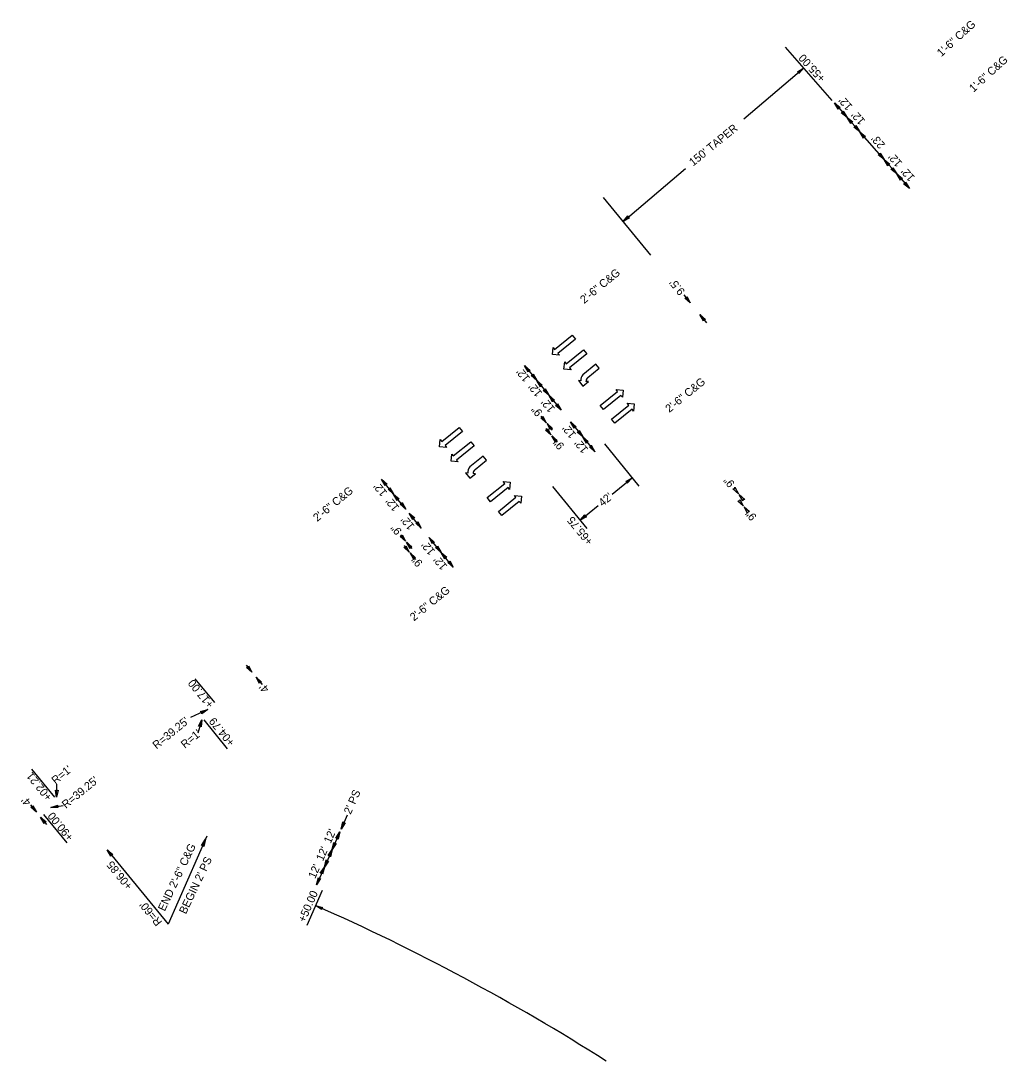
# Model space of a CAD drawing. Extents: x 2320991 to 2332664, y 598057 to 612602.
# Drawn here: x 2326449 to 2327065, y 601774 to 602424 of the extents above; entities that cross this region are included whole.
import ezdxf

# ---------------------------------------------------------------- set-up
doc = ezdxf.new("R2010")
doc.units = 0
for name, color, linetype in [('Prop Dimension', 7, 'Continuous'), ('Prop Dimension Text', 7, 'Continuous'), ('Prop Lane Arrow CELL', 7, 'Continuous'), ('Prop Terminator CELL', 7, 'Continuous')]:
    doc.layers.add(name, color=color, linetype=linetype)

msp = doc.modelspace()

# ---------------------------------------------------------------- linework, layer by layer
at = {"layer": 'Prop Dimension'}
for p, q in [((2326900.93, 602362.35), (2326938.22, 602394.1)), ((2326957.38, 602372.26), (2326965.3, 602363.24)), ((2326965.3, 602363.24), (2326973.22, 602354.23)), ((2326988.4, 602336.94), (2326973.22, 602354.23)), ((2326825.51, 602298.13), (2326864.46, 602331.29)), ((2326988.41, 602336.94), (2326996.33, 602327.92)), ((2326996.33, 602327.92), (2327004.25, 602318.91)), ((2326842.73, 602277.26), (2326813.11, 602313.14)), ((2326863.3, 602252.42), (2326867.41, 602247.39)), ((2326873.42, 602240.03), (2326877.53, 602234.99)), ((2326763.89, 602208.21), (2326771.48, 602198.91)), ((2326771.48, 602198.91), (2326779.07, 602189.62)), ((2326779.07, 602189.62), (2326786.66, 602180.32)), ((2326774.11, 602176.6), (2326777.43, 602172.54)), ((2326777.06, 602168.99), (2326780.37, 602164.93)), ((2326777.9, 602171.96), (2326781.21, 602167.9)), ((2326792.63, 602173.01), (2326800.22, 602163.71)), ((2326780.85, 602164.35), (2326784.16, 602160.3)), ((2326800.22, 602163.71), (2326807.81, 602154.41)), ((2326813.81, 602159.25), (2326835.31, 602132.9)), ((2326682.06, 602127.92), (2326674.47, 602137.21)), ((2326818.53, 602127.94), (2326831.03, 602138.15)), ((2326781.27, 602132.68), (2326802.78, 602106.34)), ((2326689.65, 602118.62), (2326682.06, 602127.92)), ((2326798.5, 602111.59), (2326809.8, 602120.82)), ((2326699.35, 602106.75), (2326691.76, 602116.05)), ((2326686.29, 602102.58), (2326689.6, 602098.53)), ((2326690.07, 602097.95), (2326693.38, 602093.89)), ((2326711.78, 602091.51), (2326704.19, 602100.8)), ((2326688.58, 602095.78), (2326691.89, 602091.73)), ((2326692.36, 602091.15), (2326695.67, 602087.09)), ((2326719.37, 602082.21), (2326711.78, 602091.51)), ((2326589.93, 602021.13), (2326593.59, 602016.64)), ((2326570.37, 601997.68), (2326558.17, 602012.63)), ((2326596.12, 602013.54), (2326599.91, 602008.9)), ((2326565.94, 601993.4), (2326555.22, 601988.4)), ((2326562.31, 601987.02), (2326559.8, 601978.66)), ((2326563.44, 601986.86), (2326578.11, 601968.9)), ((2326470.38, 601938.64), (2326456.1, 601956.13)), ((2326471.57, 601938.53), (2326471.75, 601946.76)), ((2326455.26, 601933.78), (2326458.93, 601929.3)), ((2326467.94, 601932.16), (2326475.64, 601933.45)), ((2326461.46, 601926.2), (2326465.25, 601921.55)), ((2326463.41, 601927.88), (2326477.88, 601910.15)), ((2326653.16, 601927.46), (2326649.3, 601918.71)), ((2326648.49, 601916.89), (2326643.65, 601905.91)), ((2326565.36, 601914.18), (2326541.16, 601859.27)), ((2326503.22, 601905.75), (2326541.16, 601859.27)), ((2326643.65, 601905.91), (2326638.81, 601894.93)), ((2326638.81, 601894.93), (2326633.97, 601883.94)), ((2326637.41, 601880.24), (2326627.85, 601858.55))]:
    msp.add_line(p, q, dxfattribs=at)
msp.add_lwpolyline([(2326956.07, 602373.76), (2326926.85, 602407.04)], dxfattribs=at)
msp.add_arc((2326088.93, 600635.5), 1350, 57.47144, 66.2198, dxfattribs=at)
at = {"layer": 'Prop Lane Arrow CELL'}
for p, q in [((2326782.66, 602218.35), (2326793.53, 602227.17)), ((2326793.53, 602227.17), (2326795.61, 602224.61)), ((2326795.61, 602224.61), (2326784.74, 602215.79)), ((2326781.29, 602215.05), (2326781.72, 602219.52)), ((2326785.69, 602214.62), (2326781.29, 602215.05)), ((2326781.72, 602219.52), (2326782.66, 602218.35)), ((2326784.74, 602215.79), (2326785.69, 602214.62)), ((2326789.87, 602209.3), (2326800.74, 602218.12)), ((2326802.82, 602215.56), (2326791.95, 602206.74)), ((2326800.74, 602218.12), (2326802.82, 602215.56)), ((2326788.49, 602206), (2326788.92, 602210.47)), ((2326788.92, 602210.47), (2326789.87, 602209.3)), ((2326808.45, 602209.14), (2326800.28, 602202.47)), ((2326810.54, 602206.58), (2326808.45, 602209.14)), ((2326792.89, 602205.57), (2326788.49, 602206)), ((2326791.95, 602206.74), (2326792.89, 602205.57)), ((2326803.45, 602200.8), (2326810.54, 602206.58)), ((2326798.94, 602198.66), (2326797.46, 602198.81)), ((2326797.46, 602198.81), (2326800.2, 602195.37)), ((2326800.2, 602195.37), (2326803.72, 602198.17)), ((2326803.72, 602198.17), (2326802.24, 602198.32)), ((2326811.1, 602183.28), (2326821.97, 602192.11)), ((2326824.05, 602189.54), (2326813.18, 602180.72)), ((2326821.97, 602192.11), (2326821.02, 602193.27)), ((2326821.02, 602193.27), (2326825.42, 602192.85)), ((2326824.99, 602188.38), (2326824.05, 602189.54)), ((2326825.42, 602192.85), (2326824.99, 602188.38)), ((2326813.18, 602180.72), (2326811.1, 602183.28)), ((2326818.09, 602174.71), (2326828.96, 602183.54)), ((2326828.96, 602183.54), (2326828.02, 602184.7)), ((2326828.02, 602184.7), (2326832.42, 602184.28)), ((2326832.42, 602184.28), (2326831.99, 602179.81)), ((2326831.04, 602180.97), (2326820.17, 602172.15)), ((2326831.99, 602179.81), (2326831.04, 602180.97)), ((2326712.15, 602160.79), (2326723.02, 602169.61)), ((2326723.02, 602169.61), (2326725.1, 602167.05)), ((2326820.17, 602172.15), (2326818.09, 602174.71)), ((2326725.1, 602167.05), (2326714.23, 602158.23)), ((2326710.78, 602157.48), (2326711.21, 602161.95)), ((2326715.18, 602157.06), (2326710.78, 602157.48)), ((2326711.21, 602161.95), (2326712.15, 602160.79)), ((2326714.23, 602158.23), (2326715.18, 602157.06)), ((2326719.36, 602151.74), (2326730.23, 602160.56)), ((2326732.31, 602158), (2326721.44, 602149.18)), ((2326730.23, 602160.56), (2326732.31, 602158)), ((2326717.98, 602148.43), (2326718.41, 602152.9)), ((2326718.41, 602152.9), (2326719.36, 602151.74)), ((2326721.44, 602149.18), (2326722.38, 602148.01)), ((2326737.94, 602151.58), (2326729.77, 602144.9)), ((2326740.03, 602149.02), (2326737.94, 602151.58)), ((2326722.38, 602148.01), (2326717.98, 602148.43)), ((2326732.94, 602143.23), (2326740.03, 602149.02)), ((2326728.43, 602141.1), (2326726.95, 602141.24)), ((2326726.95, 602141.24), (2326729.69, 602137.8)), ((2326729.69, 602137.8), (2326733.21, 602140.61)), ((2326733.21, 602140.61), (2326731.73, 602140.76)), ((2326740.59, 602125.72), (2326751.46, 602134.54)), ((2326753.54, 602131.98), (2326742.67, 602123.16)), ((2326751.46, 602134.54), (2326750.51, 602135.71)), ((2326750.51, 602135.71), (2326754.91, 602135.29)), ((2326754.48, 602130.82), (2326753.54, 602131.98)), ((2326754.91, 602135.29), (2326754.48, 602130.82)), ((2326742.67, 602123.16), (2326740.59, 602125.72)), ((2326747.58, 602117.15), (2326758.45, 602125.97)), ((2326760.53, 602123.41), (2326749.66, 602114.59)), ((2326758.45, 602125.97), (2326757.51, 602127.14)), ((2326757.51, 602127.14), (2326761.91, 602126.71)), ((2326761.48, 602122.25), (2326760.53, 602123.41)), ((2326761.91, 602126.71), (2326761.48, 602122.25)), ((2326749.66, 602114.59), (2326747.58, 602117.15))]:
    msp.add_line(p, q, dxfattribs=at)
for centre, radius, start, end in [((2326804.17, 602198.96), 5.25, 137.90406, 183.21576), ((2326805.5, 602198.27), 3.27, 129.22799, 178.88617), ((2326733.66, 602141.4), 5.25, 137.90406, 183.21576), ((2326734.99, 602140.7), 3.27, 129.22799, 178.88617)]:
    msp.add_arc(centre, radius, start, end, dxfattribs=at)
at = {"layer": 'Prop Terminator CELL'}
for points in [[(2326934.29, 602391.77), (2326938.22, 602394.1), (2326935.29, 602390.56), (2326935.21, 602391.54)], [(2326959.77, 602368.37), (2326957.38, 602372.26), (2326960.97, 602369.39), (2326959.99, 602369.29)], [(2326962.92, 602367.13), (2326965.3, 602363.24), (2326961.72, 602366.11), (2326962.7, 602366.21)], [(2326967.69, 602359.35), (2326965.3, 602363.24), (2326968.89, 602360.37), (2326967.91, 602360.27)], [(2326970.84, 602358.12), (2326973.22, 602354.23), (2326969.64, 602357.1), (2326970.62, 602357.19)], [(2326975.61, 602350.33), (2326973.22, 602354.23), (2326976.81, 602351.35), (2326975.83, 602351.26)], [(2326986.01, 602340.84), (2326988.4, 602336.94), (2326984.81, 602339.82), (2326985.79, 602339.91)], [(2326990.79, 602333.05), (2326988.41, 602336.94), (2326991.99, 602334.07), (2326991.01, 602333.97)], [(2326993.94, 602331.82), (2326996.33, 602327.92), (2326992.74, 602330.79), (2326993.72, 602330.89)], [(2326998.71, 602324.03), (2326996.33, 602327.92), (2326999.91, 602325.05), (2326998.93, 602324.96)], [(2327001.86, 602322.8), (2327004.25, 602318.91), (2327000.66, 602321.78), (2327001.64, 602321.88)], [(2326829.44, 602300.45), (2326825.51, 602298.13), (2326828.43, 602301.67), (2326828.51, 602300.69)], [(2326865.17, 602251.36), (2326867.41, 602247.39), (2326863.93, 602250.39), (2326864.91, 602250.45)], [(2326875.67, 602236.05), (2326873.42, 602240.03), (2326876.9, 602237.03), (2326875.92, 602236.97)], [(2326766.14, 602204.23), (2326763.89, 602208.21), (2326767.37, 602205.21), (2326766.39, 602205.15)], [(2326769.24, 602202.89), (2326771.48, 602198.91), (2326768, 602201.91), (2326768.98, 602201.97)], [(2326773.73, 602194.94), (2326771.48, 602198.91), (2326774.96, 602195.91), (2326773.98, 602195.85)], [(2326776.83, 602193.59), (2326779.07, 602189.62), (2326775.59, 602192.62), (2326776.57, 602192.68)], [(2326781.32, 602185.64), (2326779.07, 602189.62), (2326782.55, 602186.62), (2326781.57, 602186.56)], [(2326784.41, 602184.3), (2326786.66, 602180.32), (2326783.18, 602183.32), (2326784.16, 602183.38)], [(2326775.18, 602176.52), (2326777.43, 602172.54), (2326773.94, 602175.54), (2326774.93, 602175.6)], [(2326778.13, 602168.91), (2326780.37, 602164.93), (2326776.89, 602167.93), (2326777.88, 602167.99)], [(2326780.15, 602167.98), (2326777.9, 602171.96), (2326781.38, 602168.96), (2326780.4, 602168.9)], [(2326794.88, 602169.03), (2326792.63, 602173.01), (2326796.11, 602170.01), (2326795.13, 602169.95)], [(2326783.09, 602160.38), (2326780.85, 602164.35), (2326784.33, 602161.35), (2326783.35, 602161.29)], [(2326797.98, 602167.69), (2326800.22, 602163.71), (2326796.74, 602166.71), (2326797.72, 602166.77)], [(2326802.47, 602159.73), (2326800.22, 602163.71), (2326803.7, 602160.71), (2326802.72, 602160.65)], [(2326805.56, 602158.39), (2326807.81, 602154.41), (2326804.33, 602157.41), (2326805.31, 602157.47)], [(2326676.71, 602133.23), (2326674.47, 602137.21), (2326677.95, 602134.21), (2326676.97, 602134.15)], [(2326827.05, 602135.9), (2326831.03, 602138.15), (2326828.03, 602134.67), (2326827.97, 602135.65)], [(2326679.81, 602131.89), (2326682.06, 602127.92), (2326678.57, 602130.91), (2326679.56, 602130.97)], [(2326895.28, 602132.16), (2326897.53, 602128.18), (2326894.05, 602131.18), (2326895.03, 602131.24)], [(2326684.3, 602123.94), (2326682.06, 602127.92), (2326685.54, 602124.92), (2326684.55, 602124.86)], [(2326898.23, 602124.55), (2326900.48, 602120.58), (2326897, 602123.58), (2326897.98, 602123.64)], [(2326900.25, 602123.63), (2326898, 602127.6), (2326901.48, 602124.6), (2326900.5, 602124.54)], [(2326687.4, 602122.6), (2326689.65, 602118.62), (2326686.16, 602121.62), (2326687.15, 602121.68)], [(2326903.2, 602116.02), (2326900.95, 602120), (2326904.43, 602117), (2326903.45, 602116.94)], [(2326694, 602112.07), (2326691.76, 602116.05), (2326695.24, 602113.05), (2326694.26, 602112.99)], [(2326697.1, 602110.73), (2326699.35, 602106.75), (2326695.86, 602109.75), (2326696.85, 602109.81)], [(2326802.47, 602113.83), (2326798.5, 602111.59), (2326801.5, 602115.07), (2326801.56, 602114.08)], [(2326687.35, 602102.5), (2326689.6, 602098.53), (2326686.12, 602101.53), (2326687.1, 602101.59)], [(2326692.32, 602093.97), (2326690.07, 602097.95), (2326693.55, 602094.95), (2326692.57, 602094.89)], [(2326706.44, 602096.83), (2326704.19, 602100.8), (2326707.67, 602097.8), (2326706.69, 602097.74)], [(2326689.64, 602095.7), (2326691.89, 602091.73), (2326688.41, 602094.73), (2326689.39, 602094.79)], [(2326694.61, 602087.17), (2326692.36, 602091.15), (2326695.84, 602088.15), (2326694.86, 602088.09)], [(2326709.54, 602095.48), (2326711.78, 602091.51), (2326708.3, 602094.51), (2326709.28, 602094.57)], [(2326714.03, 602087.53), (2326711.78, 602091.51), (2326715.26, 602088.51), (2326714.28, 602088.45)], [(2326717.12, 602086.19), (2326719.37, 602082.21), (2326715.89, 602085.21), (2326716.87, 602085.27)], [(2326591.34, 602020.62), (2326593.59, 602016.64), (2326590.11, 602019.64), (2326591.09, 602019.7)], [(2326598.36, 602009.57), (2326596.12, 602013.54), (2326599.6, 602010.54), (2326598.62, 602010.48)], [(2326561.53, 601992.2), (2326565.94, 601993.4), (2326562.18, 601990.76), (2326562.36, 601991.73)], [(2326560.27, 601982.93), (2326562.31, 601987.02), (2326561.77, 601982.46), (2326561.17, 601983.24)], [(2326472.44, 601943.02), (2326471.57, 601938.53), (2326470.87, 601943.08), (2326471.66, 601942.48)], [(2326456.68, 601933.27), (2326458.93, 601929.3), (2326455.45, 601932.29), (2326456.43, 601932.36)], [(2326472.51, 601932.14), (2326467.94, 601932.16), (2326472.27, 601933.69), (2326471.83, 601932.81)], [(2326463.7, 601922.22), (2326461.46, 601926.2), (2326464.94, 601923.2), (2326463.96, 601923.14)], [(2326651.83, 601922.52), (2326649.3, 601918.71), (2326650.4, 601923.18), (2326650.9, 601922.33)], [(2326645.96, 601913.08), (2326648.49, 601916.89), (2326647.39, 601912.43), (2326646.89, 601913.27)], [(2326562.03, 601908.54), (2326564.55, 601912.35), (2326563.46, 601907.88), (2326562.96, 601908.73)], [(2326646.17, 601909.71), (2326643.65, 601905.91), (2326644.74, 601910.37), (2326645.24, 601909.52)], [(2326505.47, 601901.77), (2326503.22, 601905.75), (2326506.7, 601902.75), (2326505.72, 601902.69)], [(2326641.12, 601902.1), (2326643.65, 601905.91), (2326642.55, 601901.44), (2326642.05, 601902.29)], [(2326641.33, 601898.73), (2326638.81, 601894.93), (2326639.9, 601899.39), (2326640.4, 601898.54)], [(2326636.28, 601891.12), (2326638.81, 601894.93), (2326637.72, 601890.46), (2326637.22, 601891.31)], [(2326636.49, 601887.75), (2326633.97, 601883.94), (2326635.06, 601888.41), (2326635.56, 601887.56)], [(2326637.09, 601868.36), (2326633.29, 601870.88), (2326637.75, 601869.79), (2326636.9, 601869.29)]]:
    msp.add_lwpolyline(points, close=True, dxfattribs=at)

# ---------------------------------------------------------------- texts
at = {"layer": 'Prop Dimension'}
for s, rotation, p in [('+55.00', 132.37096, (2326952.16, 602388.02)), ('+17.00', 129.22799, (2326570.1, 601996.71)), ('+04.79', 129.22799, (2326583.2, 601972.97)), ('+02.21', 129.22799, (2326469.17, 601938.84)), ('+90.00', 129.22799, (2326482.48, 601913.8)), ('+06.85', 129.22799, (2326519.33, 601883.32)), ('+50.00', 66.2198, (2326626.67, 601860.01))]:
    msp.add_text(s, height=5, rotation=rotation, dxfattribs=at).set_placement(p)
at = {"layer": 'Prop Dimension Text'}
for s, rotation, p in [('1\'-6" C&G', 42.37117, (2327024.19, 602400.81)), ('1\'-6" C&G', 42.37117, (2327044.31, 602378.62)), ("12'", 131.29989, (2326969.07, 602370.19)), ("12'", 131.29989, (2326976.99, 602361.18)), ("150' TAPER", 39.22799, (2326869.16, 602332.51)), ("23'", 131.29989, (2326989.41, 602346.3)), ("12'", 131.29989, (2327000.09, 602334.87)), ("12'", 131.29989, (2327008.01, 602325.86)), ('2\'-6" C&G', 39.22799, (2326801.11, 602246.64)), ("9.5'", 129.22799, (2326864.39, 602254.64)), ("12'", 129.22799, (2326767.61, 602200.41)), ("12'", 129.22799, (2326775.2, 602191.11)), ('2\'-6" C&G', 39.22799, (2326854.31, 602178.58)), ("12'", 129.22799, (2326783.16, 602181.37)), ('9"', 129.22799, (2326775.37, 602178.95)), ("12'", 129.22799, (2326796.35, 602165.21)), ('9"', 129.22799, (2326789.04, 602158.21)), ("12'", 129.22799, (2326803.94, 602155.91)), ('9"', 129.22799, (2326895.47, 602134.6)), ('2\'-6" C&G', 39.22799, (2326634.32, 602110.48)), ("12'", 129.22799, (2326678.38, 602128.91)), ("12'", 129.22799, (2326685.97, 602119.61)), ("42'", 39.22799, (2326812.58, 602119.86)), ("12'", 129.22799, (2326695.49, 602107.97)), ('+65.75', 129.22799, (2326806.96, 602098.5)), ('9"', 129.22799, (2326909.15, 602113.86)), ('9"', 129.22799, (2326687.54, 602104.94)), ("12'", 129.22799, (2326708.31, 602092.26)), ('9"', 129.22799, (2326700.56, 602085.01)), ("12'", 129.22799, (2326715.89, 602082.96)), ('2\'-6" C&G', 39.22799, (2326694.77, 602048.34)), ("4'", 129.22799, (2326604.64, 602006.34)), ("R=39.25'", 39.22799, (2326534, 601968.34)), ("R=1'", 39.22799, (2326551.69, 601968.82)), ("R=1'", 39.22799, (2326470.92, 601946.37)), ("R=39.25'", 39.22799, (2326477.36, 601931.27)), ("2' PS", 66.2198, (2326655.23, 601927.49)), ("4'", 129.22799, (2326456.02, 601935.64)), ("12'", 66.2198, (2326642.74, 601909.34)), ('END 2\'-6" C&G', 64.56515, (2326539.1, 601867)), ("12'", 66.2198, (2326637.9, 601898.36)), ("BEGIN 2' PS", 64.56515, (2326552.29, 601865.2)), ("12'", 66.2198, (2326633.06, 601887.38)), ("R=60'", 129.22799, (2326537.79, 601860.71))]:
    msp.add_text(s, height=5, rotation=rotation, dxfattribs=at).set_placement(p)

doc.saveas('drawing.dxf')
